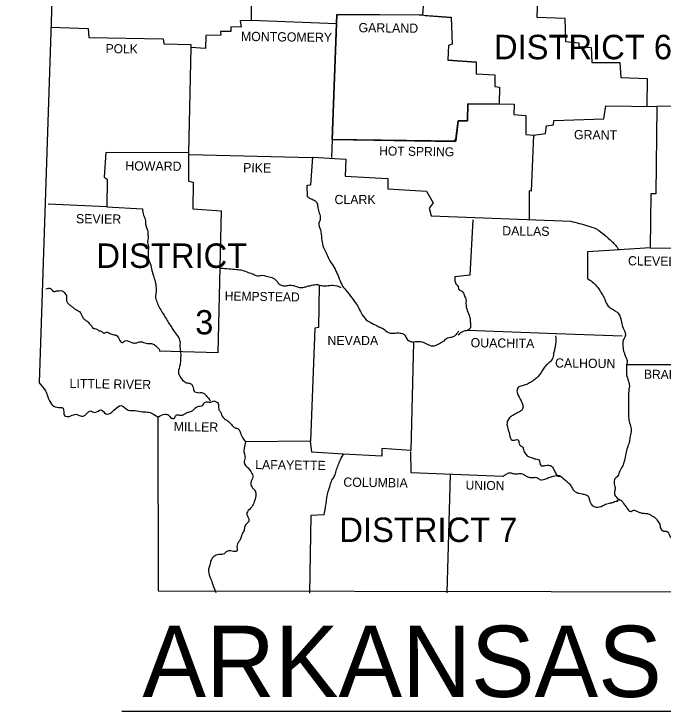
# Model space of a CAD drawing. Extents: x 1334737.7 to 1334827.2, y 402732.3 to 402753.5.
# Drawn here: x 1334820.274 to 1334823.697, y 402746.797 to 402750.474 of the extents above; entities that cross this region are included whole.
import ezdxf

# ---------------------------------------------------------------- set-up
doc = ezdxf.new("R2010")
doc.units = 0
doc.layers.add('Default', color=7, linetype='Continuous')

msp = doc.modelspace()

# ---------------------------------------------------------------- linework, layer by layer
at = {"layer": 'Default'}
for p, q in [((1334822.0098, 402748.1486), (1334822.0119, 402748.1527)), ((1334820.8432, 402746.7974), (1334825.957, 402746.7974))]:
    msp.add_line(p, q, dxfattribs=at)
for points in [[(1334820.2741, 402753.4772), (1334820.5085, 402751.5975), (1334820.4067, 402748.5291)], [(1334821.5266, 402751.1008), (1334821.5245, 402750.4396), (1334821.4679, 402750.4386), (1334821.4721, 402750.4047), (1334821.4186, 402750.4057), (1334821.4176, 402750.381), (1334821.3641, 402750.381), (1334821.3651, 402750.3625), (1334821.2859, 402750.3605), (1334821.2849, 402750.2916), (1334821.2078, 402750.2977), (1334821.1954, 402749.7414), (1334820.7594, 402749.7425), (1334820.7492, 402749.6139), (1334820.7656, 402749.6026), (1334820.7646, 402749.4576), (1334820.4551, 402749.471)], [(1334822.8099, 402750.6031), (1334822.4397, 402750.6145), (1334822.4294, 402750.4684), (1334821.9769, 402750.4715), (1334821.9749, 402750.4222)], [(1334822.9106, 402750.6073), (1334823.0371, 402750.599), (1334823.032, 402750.4571), (1334823.18, 402750.452), (1334823.1831, 402750.3286), (1334823.253, 402750.3224), (1334823.253, 402750.3019), (1334823.3189, 402750.2967), (1334823.3209, 402750.2175), (1334823.47, 402750.2175), (1334823.4741, 402750.1394), (1334823.6129, 402750.1332), (1334823.6119, 402749.9862)], [(1334821.975, 402750.4226), (1334821.5246, 402750.4401)], [(1334821.9523, 402749.8124), (1334821.9769, 402750.4715), (1334822.4294, 402750.4695)], [(1334821.9769, 402750.4654), (1334821.9831, 402750.4715)], [(1334822.4119, 402750.4695), (1334822.5795, 402750.4571), (1334822.5847, 402750.3142), (1334822.5651, 402750.308), (1334822.5631, 402750.2319), (1334822.7111, 402750.2216), (1334822.7111, 402750.1589), (1334822.8099, 402750.1538), (1334822.8109, 402750.0911), (1334822.8345, 402750.088), (1334822.8335, 402749.9985)], [(1334822.4428, 402750.4664), (1334822.5795, 402750.4561), (1334822.5847, 402750.3142), (1334822.5651, 402750.307), (1334822.5631, 402750.2309), (1334822.7111, 402750.2206), (1334822.7111, 402750.1589), (1334822.8099, 402750.1528), (1334822.8109, 402750.0911), (1334822.8345, 402750.088), (1334822.8335, 402750.0037)], [(1334820.4695, 402750.4047), (1334820.6648, 402750.3975), (1334820.669, 402750.3502), (1334821.0607, 402750.342), (1334821.0649, 402750.3173), (1334821.2078, 402750.3132), (1334821.2068, 402750.2916)], [(1334821.9749, 402750.4222), (1334821.9482, 402749.7178)], [(1334824.961, 402750.1157), (1334824.5333, 402750.127), (1334824.5312, 402749.9882), (1334823.6654, 402749.9851)], [(1334822.8335, 402749.9985), (1334822.668, 402750.0006), (1334822.6669, 402749.9101), (1334822.6165, 402749.9101), (1334822.6042, 402749.8031), (1334821.9523, 402749.8124)], [(1334821.9564, 402749.8114), (1334822.6032, 402749.8021), (1334822.6165, 402749.9101), (1334822.6669, 402749.9101), (1334822.668, 402750.0006), (1334822.9127, 402749.9975), (1334822.9106, 402749.943), (1334822.9734, 402749.9378), (1334822.9734, 402749.8391), (1334823.0145, 402749.835)], [(1334823.0145, 402749.835), (1334823.0772, 402749.8443), (1334823.0824, 402749.8833), (1334823.1194, 402749.8895), (1334823.1214, 402749.9121), (1334823.3857, 402749.9204), (1334823.395, 402749.9893), (1334823.6654, 402749.9851)], [(1334823.6654, 402749.9821), (1334823.6592, 402749.5255), (1334823.6325, 402749.5245), (1334823.6294, 402749.2407)], [(1334822.5949, 402749.8031), (1334822.6052, 402749.8144)], [(1334823.0145, 402749.835), (1334823.0011, 402749.5389), (1334822.9908, 402749.542), (1334822.9919, 402749.3887)], [(1334821.1954, 402749.7414), (1334821.1954, 402749.5913), (1334821.2201, 402749.5862), (1334821.2181, 402749.4463), (1334821.3672, 402749.435), (1334821.3497, 402748.6874), (1334821.0412, 402748.6957)], [(1334821.1975, 402749.7332), (1334821.8443, 402749.7168)], [(1334821.8227, 402749.5101), (1334821.8206, 402749.5718), (1334821.8392, 402749.5728), (1334821.8505, 402749.7188), (1334822.0242, 402749.7075), (1334822.0201, 402749.618), (1334822.2453, 402749.6057), (1334822.2464, 402749.5512), (1334822.45, 402749.5389), (1334822.4849, 402749.4782), (1334822.4633, 402749.4504), (1334822.4736, 402749.4093), (1334823.2109, 402749.3815)], [(1334820.7646, 402749.4576), (1334820.9517, 402749.4463)], [(1334822.6947, 402749.3877), (1334822.6782, 402749.0967), (1334822.6001, 402749.0874)], [(1334823.4669, 402749.2304), (1334823.2993, 402749.2201), (1334823.2983, 402749.0782)], [(1334823.6294, 402749.2407), (1334823.4638, 402749.2304)], [(1334823.6294, 402749.2407), (1334824.0294, 402749.2386)], [(1334821.8834, 402749.0443), (1334821.8803, 402748.8201), (1334821.8607, 402748.817), (1334821.8381, 402748.2216)], [(1334822.6669, 402748.8057), (1334823.1348, 402748.7892), (1334823.4824, 402748.7759)], [(1334822.3821, 402748.743), (1334822.3677, 402748.1723), (1334822.2145, 402748.1826), (1334822.2135, 402748.1414), (1334822.0119, 402748.1527)], [(1334823.505, 402748.6247), (1334824.016, 402748.6257)], [(1334821.033, 402748.3471), (1334821.035, 402747.4319), (1334825.1801, 402747.4247)], [(1334822.0119, 402748.1527), (1334821.8453, 402748.162), (1334821.8381, 402748.2216), (1334821.4947, 402748.2175)], [(1334822.852, 402748.0345), (1334822.3698, 402748.053), (1334822.3677, 402748.1671)], [(1334822.5754, 402748.0427), (1334822.5569, 402747.4216)], [(1334821.9101, 402747.8329), (1334821.8402, 402747.8288), (1334821.832, 402747.4185)]]:
    msp.add_lwpolyline(points, dxfattribs=at)
for points in [[(1334821.8227, 402749.5101), (1334821.8412, 402749.4988), (1334821.8628, 402749.4885), (1334821.8741, 402749.471), (1334821.8782, 402749.4453), (1334821.8865, 402749.4165), (1334821.8885, 402749.3877), (1334821.8823, 402749.3713), (1334821.8906, 402749.3353), (1334821.8947, 402749.3106), (1334821.8978, 402749.2808), (1334821.907, 402749.2417), (1334821.9214, 402749.2139), (1334821.9348, 402749.1821), (1334821.9574, 402749.1461), (1334821.9769, 402749.108), (1334821.9862, 402749.0874), (1334822.0027, 402749.0463), (1334822.0242, 402749.0175), (1334822.0582, 402748.9743), (1334822.089, 402748.9301), (1334822.1055, 402748.8972), (1334822.1322, 402748.8612), (1334822.161, 402748.8437), (1334822.1991, 402748.8242), (1334822.2227, 402748.8129), (1334822.2494, 402748.7934), (1334822.2844, 402748.7913), (1334822.3101, 402748.7913), (1334822.3348, 402748.781), (1334822.3461, 402748.7605), (1334822.3656, 402748.7471), (1334822.3821, 402748.743)], [(1334820.9517, 402749.4463), (1334820.9579, 402749.4124), (1334820.9682, 402749.3826), (1334820.9692, 402749.3599), (1334820.9795, 402749.326), (1334820.9795, 402749.3137), (1334820.9826, 402749.289), (1334820.9785, 402749.2756), (1334820.9836, 402749.2479), (1334820.9826, 402749.2283), (1334820.9826, 402749.2108), (1334820.9836, 402749.1831), (1334820.9929, 402749.1574), (1334821.0021, 402749.1204), (1334821.0073, 402749.1008), (1334821.0165, 402749.072), (1334821.0227, 402749.036), (1334821.0237, 402749.0083), (1334821.0206, 402748.9836), (1334821.0278, 402748.9558), (1334821.0402, 402748.927), (1334821.0566, 402748.9003), (1334821.0751, 402748.8694), (1334821.0885, 402748.8458), (1334821.106, 402748.8201), (1334821.1194, 402748.7985), (1334821.1399, 402748.7707), (1334821.1492, 402748.7481), (1334821.1492, 402748.7162), (1334821.1533, 402748.6874), (1334821.1523, 402748.6545), (1334821.1502, 402748.6247), (1334821.142, 402748.5846), (1334821.1481, 402748.5651), (1334821.1697, 402748.5373), (1334821.1831, 402748.5291), (1334821.2068, 402748.5239), (1334821.2181, 402748.5085), (1334821.2242, 402748.4849), (1334821.2489, 402748.4766), (1334821.2746, 402748.4746), (1334821.287, 402748.4612), (1334821.3044, 402748.4427), (1334821.3096, 402748.4335)], [(1334823.2109, 402749.3815), (1334823.2993, 402749.3569), (1334823.3446, 402749.3404), (1334823.3898, 402749.3075), (1334823.4268, 402749.2746), (1334823.4638, 402749.2324)], [(1334821.3651, 402749.1337), (1334821.4083, 402749.1306), (1334821.4474, 402749.1265), (1334821.4782, 402749.1224), (1334821.5101, 402749.1111), (1334821.5379, 402749.1008), (1334821.5564, 402749.0936), (1334821.5862, 402749.0957), (1334821.6129, 402749.0895), (1334821.6417, 402749.0802), (1334821.6633, 402749.0607), (1334821.6767, 402749.0463), (1334821.7034, 402749.0401), (1334821.725, 402749.0432), (1334821.7507, 402749.0412), (1334821.7805, 402749.0319), (1334821.8042, 402749.0329), (1334821.8227, 402749.0381), (1334821.8453, 402749.0432), (1334821.8741, 402749.0463), (1334821.8957, 402749.0412), (1334821.9235, 402749.0401), (1334821.9564, 402749.0432), (1334821.9975, 402749.0319)], [(1334822.6001, 402749.0874), (1334822.6001, 402749.0659), (1334822.6083, 402749.0463), (1334822.6165, 402749.0371), (1334822.6196, 402749.0216), (1334822.6299, 402749.0155), (1334822.6443, 402749.0021), (1334822.6525, 402748.9826), (1334822.6577, 402748.9702), (1334822.6577, 402748.9538), (1334822.6587, 402748.9383), (1334822.6618, 402748.9188), (1334822.6752, 402748.8849), (1334822.6782, 402748.8715), (1334822.6803, 402748.8602), (1334822.6813, 402748.8407), (1334822.6813, 402748.818), (1334822.6669, 402748.8057)], [(1334823.2983, 402749.0782), (1334823.324, 402749.0617), (1334823.3456, 402749.0391), (1334823.361, 402749.0216), (1334823.3713, 402749.0031), (1334823.3857, 402748.9805), (1334823.4042, 402748.9373), (1334823.4217, 402748.9229), (1334823.4453, 402748.9075), (1334823.4597, 402748.8972), (1334823.4741, 402748.8653), (1334823.4813, 402748.8324), (1334823.4937, 402748.8026), (1334823.4998, 402748.78), (1334823.4896, 402748.7574), (1334823.4865, 402748.7121), (1334823.4937, 402748.6813), (1334823.5029, 402748.6587), (1334823.5081, 402748.6329), (1334823.505, 402748.6247)], [(1334820.4417, 402749.0247), (1334820.4674, 402749.0257), (1334820.4839, 402749.0103), (1334820.4942, 402749.0124), (1334820.5127, 402749.0144), (1334820.5291, 402749.0134), (1334820.5415, 402749.0031), (1334820.5517, 402748.9846), (1334820.5507, 402748.9682), (1334820.5517, 402748.961), (1334820.56, 402748.9466), (1334820.5733, 402748.9353), (1334820.5877, 402748.9239), (1334820.6011, 402748.9147), (1334820.6237, 402748.9003), (1334820.6268, 402748.8952), (1334820.635, 402748.8777), (1334820.6463, 402748.8623), (1334820.6607, 402748.854), (1334820.6751, 402748.8376), (1334820.6813, 402748.8314), (1334820.6936, 402748.815), (1334820.706, 402748.8139), (1334820.7224, 402748.8036), (1334820.7348, 402748.8006), (1334820.7481, 402748.7913), (1334820.7625, 402748.7954), (1334820.779, 402748.7892), (1334820.8016, 402748.782), (1334820.8139, 402748.78), (1334820.8294, 402748.7584), (1334820.8438, 402748.7409), (1334820.8613, 402748.7502), (1334820.8952, 402748.7409), (1334820.9168, 402748.7389), (1334820.9363, 402748.745), (1334820.9507, 402748.744), (1334820.9785, 402748.7368), (1334820.9949, 402748.7368), (1334821.0134, 402748.7306), (1334821.0299, 402748.7162), (1334821.0412, 402748.7018), (1334821.0412, 402748.6957)], [(1334822.6207, 402748.8006), (1334822.6083, 402748.7862), (1334822.5939, 402748.7728), (1334822.5764, 402748.7676), (1334822.561, 402748.7635), (1334822.5404, 402748.7491), (1334822.524, 402748.7378), (1334822.5034, 402748.7275), (1334822.4829, 402748.7214), (1334822.4582, 402748.7296), (1334822.4438, 402748.7368), (1334822.4294, 402748.743), (1334822.3821, 402748.743)], [(1334822.6165, 402748.782), (1334822.6453, 402748.8016), (1334822.6782, 402748.8057)], [(1334823.1307, 402748.7759), (1334823.1286, 402748.7193), (1334823.1204, 402748.6844), (1334823.1122, 402748.6525), (1334823.0957, 402748.634), (1334823.0772, 402748.6165), (1334823.0608, 402748.5959), (1334823.0464, 402748.5712), (1334823.0309, 402748.5548), (1334823.0114, 402748.5394), (1334822.9929, 402748.5281), (1334822.9713, 402748.5178), (1334822.9476, 402748.5116), (1334822.9302, 402748.4993), (1334822.9291, 402748.4725), (1334822.9487, 402748.4335), (1334822.9559, 402748.416), (1334822.9579, 402748.3944), (1334822.9497, 402748.382), (1334822.9312, 402748.3718), (1334822.9106, 402748.3594), (1334822.8911, 402748.3481), (1334822.8777, 402748.3286), (1334822.8746, 402748.3029), (1334822.8839, 402748.272), (1334822.888, 402748.2545), (1334822.9024, 402748.2257), (1334822.9137, 402748.2268), (1334822.9343, 402748.2257), (1334822.9363, 402748.2206), (1334822.9374, 402748.2144), (1334822.9415, 402748.2), (1334822.959, 402748.1877), (1334822.961, 402748.1764), (1334822.9713, 402748.1548), (1334822.9878, 402748.1394), (1334823.0011, 402748.1353), (1334823.0268, 402748.127), (1334823.0402, 402748.1239), (1334823.0546, 402748.091), (1334823.0731, 402748.0921), (1334823.0865, 402748.0941), (1334823.1091, 402748.089), (1334823.1194, 402748.0756), (1334823.1297, 402748.053), (1334823.143, 402748.0365), (1334823.1523, 402748.0365)], [(1334823.505, 402748.6247), (1334823.5091, 402748.5548), (1334823.5194, 402748.5209), (1334823.5163, 402748.4849), (1334823.5153, 402748.4499), (1334823.5153, 402748.418), (1334823.5153, 402748.3872), (1334823.5153, 402748.3563), (1334823.5173, 402748.3337), (1334823.5255, 402748.3008), (1334823.5286, 402748.27), (1334823.5225, 402748.2401), (1334823.5183, 402748.2134), (1334823.5091, 402748.1867), (1334823.5019, 402748.1558), (1334823.4926, 402748.1157), (1334823.4844, 402748.09), (1334823.469, 402748.0633), (1334823.4587, 402748.0376), (1334823.4433, 402748.0221), (1334823.4402, 402747.9954), (1334823.4443, 402747.9697), (1334823.4412, 402747.9471), (1334823.4495, 402747.9265), (1334823.47, 402747.9111)], [(1334820.4067, 402748.5291), (1334820.4397, 402748.4859), (1334820.453, 402748.455), (1334820.4726, 402748.416), (1334820.5003, 402748.3995), (1334820.5332, 402748.3944), (1334820.5404, 402748.3563), (1334820.5744, 402748.3543), (1334820.6011, 402748.3625), (1334820.6391, 402748.3522), (1334820.6782, 402748.38), (1334820.7008, 402748.3728), (1334820.7337, 402748.3862), (1334820.7584, 402748.3656), (1334820.8016, 402748.3841), (1334820.8397, 402748.4088), (1334820.8767, 402748.3851), (1334820.9116, 402748.382), (1334820.9528, 402748.3759), (1334820.9857, 402748.3738), (1334821.0155, 402748.3594), (1334821.0371, 402748.345), (1334821.033, 402748.3471)], [(1334821.033, 402748.3471), (1334821.072, 402748.3635), (1334821.0885, 402748.3584), (1334821.1039, 402748.343), (1334821.1204, 402748.343), (1334821.1296, 402748.3574), (1334821.1471, 402748.3584), (1334821.1605, 402748.3574), (1334821.1749, 402748.3656), (1334821.1872, 402748.3718), (1334821.2047, 402748.3769), (1334821.217, 402748.382), (1334821.2284, 402748.3944), (1334821.2489, 402748.4047), (1334821.2726, 402748.4129), (1334821.2787, 402748.4242), (1334821.29, 402748.4283), (1334821.3127, 402748.4273), (1334821.3281, 402748.4335), (1334821.3404, 402748.4283), (1334821.3517, 402748.4201), (1334821.3538, 402748.3913), (1334821.3631, 402748.3748), (1334821.3764, 402748.3471), (1334821.396, 402748.3317), (1334821.4134, 402748.3173), (1334821.4206, 402748.308), (1334821.4402, 402748.2916), (1334821.4566, 402748.2854), (1334821.4649, 402748.273), (1334821.4772, 402748.2443), (1334821.4947, 402748.2175)], [(1334821.4947, 402748.2175), (1334821.4885, 402748.1846), (1334821.4875, 402748.1589), (1334821.4926, 402748.1281), (1334821.4875, 402748.1137), (1334821.4957, 402748.0921), (1334821.5132, 402748.0756), (1334821.5255, 402748.0571), (1334821.5338, 402748.0314), (1334821.5235, 402748.0016), (1334821.5348, 402747.9718), (1334821.5451, 402747.9604), (1334821.5502, 402747.9419), (1334821.543, 402747.907), (1334821.5327, 402747.8813), (1334821.5101, 402747.8545), (1334821.5029, 402747.8422), (1334821.506, 402747.8257), (1334821.5122, 402747.798), (1334821.506, 402747.7908), (1334821.4916, 402747.7712), (1334821.4875, 402747.7496), (1334821.4772, 402747.7311), (1334821.4659, 402747.6982), (1334821.4505, 402747.6715), (1334821.4484, 402747.6406), (1334821.4258, 402747.6406), (1334821.4001, 402747.6406), (1334821.3764, 402747.6242), (1334821.3548, 402747.6232), (1334821.3291, 402747.6129), (1334821.3127, 402747.5913), (1334821.3075, 402747.5676), (1334821.3003, 402747.545), (1334821.3075, 402747.5059), (1334821.3178, 402747.4792), (1334821.325, 402747.4576), (1334821.3394, 402747.4226)], [(1334821.9101, 402747.8329), (1334821.9163, 402747.87), (1334821.9214, 402747.8977), (1334821.9245, 402747.9245), (1334821.9317, 402747.9553), (1334821.942, 402747.9882), (1334821.9512, 402748.0149), (1334821.9636, 402748.0345), (1334821.9708, 402748.0571), (1334821.9811, 402748.0849), (1334821.9913, 402748.1126), (1334822.0098, 402748.1486)], [(1334822.852, 402748.0345), (1334822.8705, 402748.0468), (1334822.888, 402748.054), (1334822.9045, 402748.0509), (1334822.923, 402748.0478), (1334822.9384, 402748.0509), (1334822.959, 402748.0468), (1334822.9754, 402748.0365), (1334822.9949, 402748.0293), (1334823.0145, 402748.0293), (1334823.0309, 402748.0293), (1334823.0464, 402748.0191), (1334823.0731, 402748.0201), (1334823.0957, 402748.0293), (1334823.1183, 402748.0355), (1334823.1492, 402748.0396), (1334823.1759, 402748.0201), (1334823.1955, 402748.0036), (1334823.2109, 402747.9861), (1334823.2222, 402747.9656), (1334823.2345, 402747.9543), (1334823.2551, 402747.946), (1334823.2705, 402747.943), (1334823.2901, 402747.9378), (1334823.3004, 402747.9327), (1334823.3096, 402747.9111), (1334823.324, 402747.8823), (1334823.3528, 402747.872), (1334823.3878, 402747.8854), (1334823.4155, 402747.8936), (1334823.4361, 402747.8998), (1334823.4484, 402747.9049), (1334823.4597, 402747.9059), (1334823.4567, 402747.908), (1334823.47, 402747.9111), (1334823.4824, 402747.9018), (1334823.4906, 402747.8895), (1334823.504, 402747.872), (1334823.5163, 402747.8556), (1334823.5286, 402747.8504), (1334823.541, 402747.8566), (1334823.5585, 402747.8514), (1334823.5728, 402747.8453), (1334823.5903, 402747.8412), (1334823.6047, 402747.8401), (1334823.6243, 402747.836), (1334823.6387, 402747.8278), (1334823.652, 402747.8196), (1334823.6654, 402747.8052), (1334823.6798, 402747.7825), (1334823.6839, 402747.764), (1334823.6993, 402747.7466), (1334823.7148, 402747.7466), (1334823.7353, 402747.7167), (1334823.7435, 402747.7054), (1334823.761, 402747.6849), (1334823.7734, 402747.6849), (1334823.797, 402747.6807)]]:
    msp.add_spline(points, degree=3, dxfattribs=at)

# ---------------------------------------------------------------- texts
for s, height, rotation, p in [('GARLAND', 0.04864, 359.3658, (1334822.0911, 402750.3779)), ('MONTGOMERY', 0.04864, 359.2944, (1334821.471, 402750.3317)), ('POLK', 0.04749, 359.2152, (1334820.7574, 402750.2679)), ('GRANT', 0.04864, 359.4032, (1334823.2273, 402749.8134)), ('HOT SPRING', 0.04751, 359.2216, (1334822.2001, 402749.7281)), ('HOWARD', 0.04864, 359.5145, (1334820.8613, 402749.6489)), ('PIKE', 0.04863, 359.0452, (1334821.4823, 402749.6396)), ('SEVIER', 0.04864, 359.4271, (1334820.6011, 402749.3702)), ('DALLAS', 0.04863, 359.2462, (1334822.8489, 402749.3065)), ('CLEVELAND', 0.04864, 359.3376, (1334823.5122, 402749.1481)), ('HEMPSTEAD', 0.04749, 359.1885, (1334821.3857, 402748.963)), ('OUACHITA', 0.04864, 359.2043, (1334822.6823, 402748.7162)), ('CALHOUN', 0.04864, 359.3634, (1334823.1276, 402748.6093)), ('BRADLEY', 0.04749, 359.1449, (1334823.5965, 402748.5507)), ('LITTLE RIVER', 0.048642, 359.1697, (1334820.5672, 402748.5013)), ('MILLER', 0.04863, 359.1319, (1334821.1163, 402748.2741)), ('LAFAYETTE', 0.04863, 359.1839, (1334821.5461, 402748.0736)), ('COLUMBIA', 0.04863, 359.2125, (1334822.0109, 402747.981)), ('UNION', 0.04751, 358.9584, (1334822.6556, 402747.9656))]:
    msp.add_text(s, height=height, rotation=rotation, dxfattribs=at).set_placement(p)
for s, height, p in [('DISTRICT 6', 0.12895, (1334822.8057, 402750.235)), ('CLARK', 0.04864, (1334821.9646, 402749.471)), ('DISTRICT', 0.12895, (1334820.7091, 402749.1347)), ('3', 0.1278, (1334821.2304, 402748.7841)), ('NEVADA', 0.04864, (1334821.9276, 402748.7275)), ('DISTRICT 7', 0.12895, (1334821.9903, 402747.689)), ('ARKANSAS HWY. DIST. 10', 0.376088, (1334820.9517, 402746.8715))]:
    msp.add_text(s, height=height, dxfattribs=at).set_placement(p)

doc.saveas('drawing.dxf')
